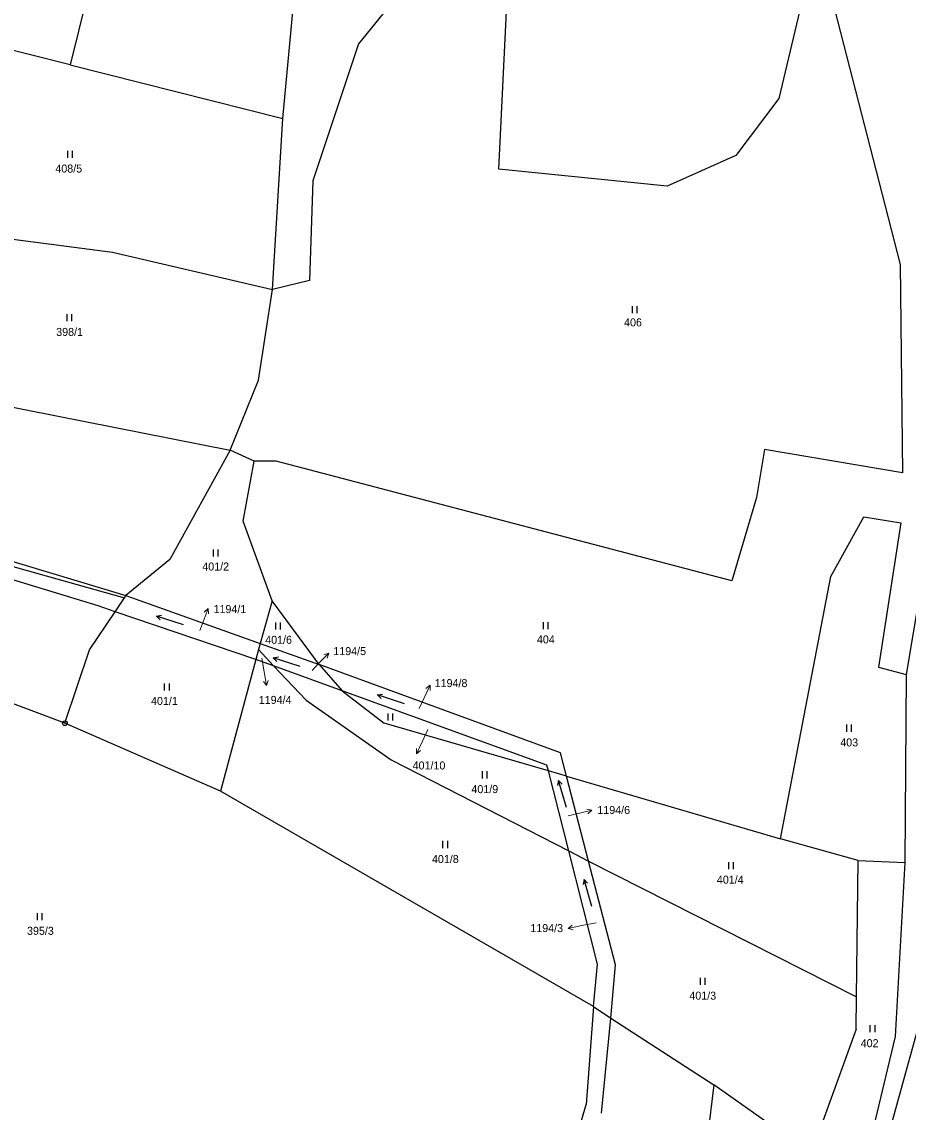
# Model space of a CAD drawing. Extents: x -765428 to -762163, y -1107632 to -1104975.
# Drawn here: x -764245.3 to -764056.9, y -1106600.1 to -1106368.4 of the extents above; entities that cross this region are included whole.
import ezdxf
from ezdxf.enums import TextEntityAlignment as Align

# ---------------------------------------------------------------- set-up
doc = ezdxf.new("R2010")
doc.units = 0
doc.header["$LTSCALE"] = 0.68
for name, color, linetype, lineweight in [('1', 7, 'Continuous', 25), ('3', 7, 'Continuous', 25), ('7', 7, 'Continuous', 13), ('8', 7, 'Continuous', 25)]:
    doc.layers.add(name, color=color, linetype=linetype, lineweight=lineweight)
doc.layers.add('2', color=7, linetype='Continuous')

msp = doc.modelspace()

# ---------------------------------------------------------------- linework, layer by layer
at = {"layer": '1'}
for p, q in [((-764211.87, -1106285.29), (-764235, -1106377.55)), ((-764143.9, -1106399.69), (-764139.84, -1106316.48)), ((-764189.79, -1106388.96), (-764185.51, -1106343.31)), ((-764075.62, -1106347.92), (-764084.46, -1106384.7)), ((-764156.33, -1106351.7), (-764173.73, -1106373.07)), ((-764074.89, -1106356.64), (-764058.65, -1106419.96)), ((-764235, -1106377.55), (-764269.3, -1106368.85)), ((-764173.73, -1106373.07), (-764183.39, -1106402.22)), ((-764235, -1106377.55), (-764189.79, -1106388.96)), ((-764084.46, -1106384.7), (-764093.59, -1106396.8)), ((-764191.97, -1106425.28), (-764189.79, -1106388.96)), ((-764093.59, -1106396.8), (-764108.16, -1106403.35)), ((-764108.16, -1106403.35), (-764143.9, -1106399.69)), ((-764276.16, -1106410.77), (-764226.01, -1106417.33)), ((-764226.01, -1106417.33), (-764191.97, -1106425.28)), ((-764058.65, -1106419.96), (-764058.18, -1106464.22)), ((-764195, -1106444.56), (-764191.97, -1106425.28)), ((-764278.87, -1106444.01), (-764201.01, -1106459.45)), ((-764201.01, -1106459.45), (-764195, -1106444.56)), ((-764201.01, -1106459.45), (-764213.83, -1106482.66)), ((-764195.91, -1106461.73), (-764201.01, -1106459.45)), ((-764087.49, -1106459.28), (-764089.16, -1106469.49)), ((-764058.18, -1106464.22), (-764087.49, -1106459.28)), ((-764198.19, -1106474.47), (-764195.91, -1106461.73)), ((-764191.18, -1106461.74), (-764195.91, -1106461.73)), ((-764094.43, -1106487.16), (-764191.18, -1106461.74)), ((-764050.86, -1106468.04), (-764057.38, -1106507.08)), ((-764297.32, -1106470.07), (-764223.46, -1106490.82)), ((-764089.16, -1106469.49), (-764094.43, -1106487.16)), ((-764073.39, -1106486.23), (-764066.39, -1106473.61)), ((-764066.39, -1106473.61), (-764058.49, -1106474.83)), ((-764192.08, -1106491.43), (-764198.19, -1106474.47)), ((-764058.49, -1106474.83), (-764063.26, -1106505.54)), ((-764263.3, -1106478.21), (-764223.12, -1106490.32)), ((-764229.04, -1106492.51), (-764263.78, -1106481.96)), ((-764213.83, -1106482.66), (-764223.12, -1106490.32)), ((-764084.1, -1106541.99), (-764073.39, -1106486.23)), ((-764225.43, -1106493.73), (-764223.46, -1106490.82)), ((-764223.46, -1106490.82), (-764223.12, -1106490.32)), ((-764223.12, -1106490.32), (-764194.59, -1106500.49)), ((-764192.08, -1106491.43), (-764194.59, -1106500.49)), ((-764182.1, -1106504.95), (-764192.08, -1106491.43)), ((-764230.89, -1106501.82), (-764225.43, -1106493.73)), ((-764236.11, -1106517.44), (-764290.36, -1106497)), ((-764194.59, -1106500.49), (-764194.95, -1106501.78)), ((-764194.59, -1106500.49), (-764182.1, -1106504.95)), ((-764236.11, -1106517.44), (-764230.89, -1106501.82)), ((-764195.53, -1106503.87), (-764203.06, -1106531.88)), ((-764194.95, -1106501.78), (-764195.53, -1106503.87)), ((-764191.79, -1106505.23), (-764195.53, -1106503.87)), ((-764191.79, -1106505.23), (-764194.95, -1106501.78)), ((-764184.81, -1106512.52), (-764191.79, -1106505.23)), ((-764177.18, -1106510.54), (-764191.79, -1106505.23)), ((-764182.1, -1106504.95), (-764177.18, -1106510.54)), ((-764130.84, -1106523.7), (-764182.1, -1106504.95)), ((-764063.26, -1106505.54), (-764057.38, -1106507.08)), ((-764057.38, -1106507.08), (-764057.69, -1106546.99)), ((-764177.18, -1106510.54), (-764168.25, -1106517.43)), ((-764133.69, -1106526.34), (-764177.18, -1106510.54)), ((-764184.81, -1106512.52), (-764166.79, -1106525.18)), ((-764203.06, -1106531.88), (-764236.11, -1106517.44)), ((-764133.38, -1106527.54), (-764168.25, -1106517.43)), ((-764129.52, -1106528.66), (-764130.84, -1106523.7)), ((-764166.79, -1106525.18), (-764129.05, -1106544.55)), ((-764133.38, -1106527.54), (-764133.69, -1106526.34)), ((-764129.52, -1106528.66), (-764133.38, -1106527.54)), ((-764129.05, -1106544.55), (-764133.38, -1106527.54)), ((-764124.84, -1106546.71), (-764129.52, -1106528.66)), ((-764129.52, -1106528.66), (-764084.1, -1106541.99)), ((-764123.81, -1106577.61), (-764203.06, -1106531.88)), ((-764067.55, -1106546.59), (-764084.1, -1106541.99)), ((-764122.92, -1106568.62), (-764129.05, -1106544.55)), ((-764129.05, -1106544.55), (-764124.84, -1106546.71)), ((-764119.13, -1106568.77), (-764124.84, -1106546.71)), ((-764124.84, -1106546.71), (-764067.91, -1106575.59)), ((-764067.91, -1106575.59), (-764067.55, -1106546.59)), ((-764067.55, -1106546.59), (-764057.69, -1106546.99)), ((-764057.69, -1106546.99), (-764059.71, -1106583.99)), ((-764123.81, -1106577.61), (-764122.92, -1106568.62)), ((-764120.1, -1106580.06), (-764119.13, -1106568.77)), ((-764068, -1106582.41), (-764067.91, -1106575.59)), ((-764123.81, -1106577.61), (-764125.34, -1106598.43)), ((-764123.81, -1106577.61), (-764120.1, -1106580.06)), ((-764053.62, -1106577.6), (-764062.34, -1106609.21)), ((-764122.07, -1106600.28), (-764120.1, -1106580.06)), ((-764120.1, -1106580.06), (-764098.26, -1106594.25)), ((-764068, -1106582.41), (-764076.95, -1106607.17)), ((-764059.71, -1106583.99), (-764065.69, -1106609.05)), ((-764098.26, -1106594.25), (-764100.05, -1106609.19)), ((-764080.83, -1106606.52), (-764098.26, -1106594.25)), ((-764132.16, -1106622.12), (-764125.34, -1106598.43))]:
    msp.add_line(p, q, dxfattribs=at)
for points in [[(-764183.39, -1106402.22), (-764184.15, -1106423.35), (-764191.97, -1106425.28)], [(-764195.53, -1106503.87), (-764225.43, -1106493.73), (-764229.04, -1106492.51)]]:
    msp.add_lwpolyline(points, dxfattribs=at)
at = {"layer": '3'}
for p, q in [((-764235.471, -1106397.32), (-764235.471, -1106395.82)), ((-764234.47, -1106397.32), (-764234.47, -1106395.82)), ((-764115.531, -1106430.3), (-764115.531, -1106428.8)), ((-764114.53, -1106430.3), (-764114.53, -1106428.8)), ((-764235.611, -1106432.02), (-764235.611, -1106430.52)), ((-764234.61, -1106432.02), (-764234.61, -1106430.52)), ((-764204.541, -1106481.99), (-764204.541, -1106480.49)), ((-764203.54, -1106481.99), (-764203.54, -1106480.49)), ((-764216.627, -1106494.68), (-764215.543, -1106494.505)), ((-764191.311, -1106497.53), (-764191.311, -1106496.03)), ((-764190.31, -1106497.53), (-764190.31, -1106496.03)), ((-764134.451, -1106497.47), (-764134.451, -1106495.97)), ((-764133.45, -1106497.47), (-764133.45, -1106495.97)), ((-764191.837, -1106503.53), (-764190.753, -1106503.355)), ((-764214.911, -1106510.47), (-764214.911, -1106508.97)), ((-764213.91, -1106510.47), (-764213.91, -1106508.97)), ((-764169.677, -1106511.43), (-764168.593, -1106511.255)), ((-764167.441, -1106516.86), (-764167.441, -1106515.36)), ((-764166.44, -1106516.86), (-764166.44, -1106515.36)), ((-764069.991, -1106519.23), (-764069.991, -1106517.73)), ((-764068.99, -1106519.23), (-764068.99, -1106517.73)), ((-764147.401, -1106529.15), (-764147.401, -1106527.65)), ((-764146.4, -1106529.15), (-764146.4, -1106527.65)), ((-764131.203, -1106529.577), (-764130.452, -1106530.378)), ((-764155.781, -1106543.95), (-764155.781, -1106542.45)), ((-764154.78, -1106543.95), (-764154.78, -1106542.45)), ((-764095.071, -1106548.42), (-764095.071, -1106546.92)), ((-764094.07, -1106548.42), (-764094.07, -1106546.92)), ((-764125.793, -1106550.627), (-764125.042, -1106551.428)), ((-764241.941, -1106559.3), (-764241.941, -1106557.8)), ((-764240.94, -1106559.3), (-764240.94, -1106557.8)), ((-764101.101, -1106573.03), (-764101.101, -1106571.53)), ((-764100.1, -1106573.03), (-764100.1, -1106571.53)), ((-764064.991, -1106583.09), (-764064.991, -1106581.59)), ((-764063.99, -1106583.09), (-764063.99, -1106581.59))]:
    msp.add_line(p, q, dxfattribs=at)
for points in [[(-764210.92, -1106496.534), (-764216.627, -1106494.68), (-764215.852, -1106495.458)], [(-764186.13, -1106505.384), (-764191.837, -1106503.53), (-764191.062, -1106504.308)], [(-764163.97, -1106513.284), (-764169.677, -1106511.43), (-764168.902, -1106512.208)], [(-764129.55, -1106535.345), (-764131.203, -1106529.577), (-764131.416, -1106530.655)], [(-764124.14, -1106556.395), (-764125.793, -1106550.627), (-764126.006, -1106551.705)]]:
    msp.add_lwpolyline(points, dxfattribs=at)
at = {"layer": '7'}
for p, q in [((-764205.665, -1106493.088), (-764206.491, -1106493.844)), ((-764180.055, -1106502.541), (-764181.111, -1106502.914)), ((-764193.259, -1106509.445), (-764192.94, -1106508.372)), ((-764158.522, -1106509.34), (-764159.399, -1106510.036)), ((-764161.398, -1106523.93), (-764160.521, -1106523.234)), ((-764124.136, -1106535.935), (-764125.224, -1106535.672)), ((-764129.196, -1106561.013), (-764128.117, -1106561.313))]:
    msp.add_line(p, q, dxfattribs=at)
for points in [[(-764207.44, -1106497.74), (-764206.74, -1106495.89), (-764205.665, -1106493.088), (-764205.556, -1106494.203)], [(-764194.29, -1106503.62), (-764193.78, -1106506.49), (-764193.259, -1106509.445), (-764193.926, -1106508.546)], [(-764183.59, -1106506.23), (-764182.14, -1106504.7), (-764180.055, -1106502.541), (-764180.391, -1106503.61)], [(-764160.81, -1106514.28), (-764159.79, -1106512.06), (-764158.522, -1106509.34), (-764158.491, -1106510.459)], [(-764158.96, -1106518.73), (-764160.13, -1106521.21), (-764161.398, -1106523.93), (-764161.429, -1106522.811)], [(-764129.18, -1106537.09), (-764127.06, -1106536.61), (-764124.136, -1106535.935), (-764124.999, -1106536.648)], [(-764123.2, -1106559.86), (-764126.25, -1106560.44), (-764129.196, -1106561.013), (-764128.308, -1106560.33)]]:
    msp.add_lwpolyline(points, dxfattribs=at)
at = {"layer": '8'}
for radius in [0.5, 0.0303]:
    msp.add_circle((-764236.11, -1106517.4399), radius, dxfattribs=at)

# ---------------------------------------------------------------- texts
at = {"layer": '2'}
for s, p in [('408/5', (-764235.28, -1106400.435)), ('398/1', (-764235.1, -1106435.145)), ('401/2', (-764204.06, -1106484.985)), ('401/6', (-764190.7, -1106500.555)), ('401/1', (-764214.95, -1106513.545)), ('403', (-764069.479, -1106522.355)), ('401/9', (-764146.89, -1106532.275)), ('401/8', (-764155.27, -1106547.135)), ('401/4', (-764094.74, -1106551.515)), ('395/3', (-764241.3, -1106562.385)), ('401/3', (-764100.59, -1106576.155))]:
    msp.add_text(s, height=1.7, dxfattribs=at).set_placement(p, align=Align.CENTER)
for s, p in [('406', (-764117.3, -1106433.115)), ('1194/1', (-764204.52, -1106494.025)), ('404', (-764135.82, -1106500.475)), ('1194/5', (-764179.07, -1106502.955)), ('1194/8', (-764157.54, -1106509.755)), ('1194/4', (-764194.91, -1106513.325)), ('1194/6', (-764122.98, -1106536.715)), ('402', (-764067.03, -1106586.255))]:
    msp.add_text(s, height=1.7, dxfattribs=at).set_placement(p)
for s, p in [('401/10', (-764155.269, -1106527.255)), ('1194/3', (-764130.269, -1106561.805))]:
    msp.add_text(s, height=1.7, dxfattribs=at).set_placement(p, align=Align.RIGHT)

doc.saveas('drawing.dxf')
